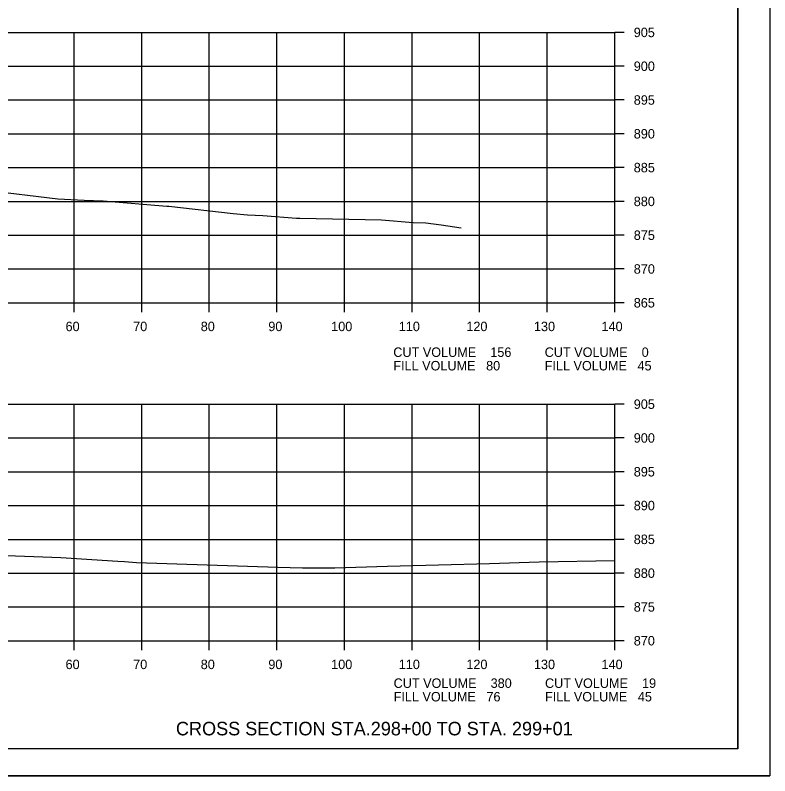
# Model space of a CAD drawing. Extents: x 1486524 to 1499135, y 326561 to 337924.
# Drawn here: x 1489034.2 to 1489145.8, y 333632.7 to 333745.2 of the extents above; entities that cross this region are included whole.
import ezdxf

# ---------------------------------------------------------------- set-up
doc = ezdxf.new("R2010")
doc.units = 0
for name, color, linetype in [('E_Const Align', 7, 'Continuous'), ('E_Const Align Station', 7, 'Continuous'), ('E_Ownership Information', 7, 'Continuous'), ('E_Property Line', 7, 'Continuous'), ('E_Proposed ROW Fig Annot', 7, 'Continuous'), ('E_Quarter Calls', 7, 'Continuous'), ('E_Tract Number', 7, 'Continuous')]:
    doc.layers.add(name, color=color, linetype=linetype)

msp = doc.modelspace()

# ---------------------------------------------------------------- linework, layer by layer
at = {"layer": 'E_Const Align'}
for p, q in [((1489122.89, 333702.64), (1489122.89, 333742.64)), ((1489124.29, 333742.64), (1489122.89, 333742.64)), ((1489124.29, 333737.64), (1489122.89, 333737.64)), ((1489124.29, 333732.64), (1489122.89, 333732.64)), ((1489124.29, 333727.64), (1489122.89, 333727.64)), ((1489124.29, 333722.64), (1489122.89, 333722.64)), ((1489124.29, 333717.64), (1489122.89, 333717.64)), ((1489124.29, 333712.64), (1489122.89, 333712.64)), ((1489124.29, 333707.64), (1489122.89, 333707.64)), ((1488842.89, 333702.64), (1489122.89, 333702.64)), ((1489042.89, 333701.24), (1489042.89, 333702.64)), ((1489052.89, 333701.24), (1489052.89, 333702.64)), ((1489062.89, 333701.24), (1489062.89, 333702.64)), ((1489072.89, 333701.24), (1489072.89, 333702.64)), ((1489082.89, 333701.24), (1489082.89, 333702.64)), ((1489092.89, 333701.24), (1489092.89, 333702.64)), ((1489102.89, 333701.24), (1489102.89, 333702.64)), ((1489112.89, 333701.24), (1489112.89, 333702.64)), ((1489122.89, 333701.24), (1489122.89, 333702.64)), ((1489124.29, 333702.64), (1489122.89, 333702.64)), ((1489122.89, 333652.64), (1489122.89, 333687.64)), ((1489124.29, 333687.64), (1489122.89, 333687.64)), ((1489124.29, 333682.64), (1489122.89, 333682.64)), ((1489124.29, 333677.64), (1489122.89, 333677.64)), ((1489124.29, 333672.64), (1489122.89, 333672.64)), ((1489124.29, 333667.64), (1489122.89, 333667.64)), ((1489124.29, 333662.64), (1489122.89, 333662.64)), ((1489124.29, 333657.64), (1489122.89, 333657.64)), ((1488842.89, 333652.64), (1489122.89, 333652.64)), ((1489042.89, 333651.24), (1489042.89, 333652.64)), ((1489052.89, 333651.24), (1489052.89, 333652.64)), ((1489062.89, 333651.24), (1489062.89, 333652.64)), ((1489072.89, 333651.24), (1489072.89, 333652.64)), ((1489082.89, 333651.24), (1489082.89, 333652.64)), ((1489092.89, 333651.24), (1489092.89, 333652.64)), ((1489102.89, 333651.24), (1489102.89, 333652.64)), ((1489112.89, 333651.24), (1489112.89, 333652.64)), ((1489122.89, 333651.24), (1489122.89, 333652.64)), ((1489124.29, 333652.64), (1489122.89, 333652.64))]:
    msp.add_line(p, q, dxfattribs=at)
at = {"layer": 'E_Ownership Information'}
for p, q in [((1488842.89, 333742.64), (1489122.89, 333742.64)), ((1489042.89, 333702.64), (1489042.89, 333742.64)), ((1489052.89, 333702.64), (1489052.89, 333742.64)), ((1489062.89, 333702.64), (1489062.89, 333742.64)), ((1489072.89, 333702.64), (1489072.89, 333742.64)), ((1489082.89, 333702.64), (1489082.89, 333742.64)), ((1489092.89, 333702.64), (1489092.89, 333742.64)), ((1489102.89, 333702.64), (1489102.89, 333742.64)), ((1489112.89, 333702.64), (1489112.89, 333742.64)), ((1489122.89, 333702.64), (1489122.89, 333742.64)), ((1488842.89, 333737.64), (1489122.89, 333737.64)), ((1488842.89, 333732.64), (1489122.89, 333732.64)), ((1488842.89, 333727.64), (1489122.89, 333727.64)), ((1488842.89, 333722.64), (1489122.89, 333722.64)), ((1488842.89, 333717.64), (1489122.89, 333717.64)), ((1488842.89, 333712.64), (1489122.89, 333712.64)), ((1488842.89, 333707.64), (1489122.89, 333707.64)), ((1488842.89, 333702.64), (1489122.89, 333702.64)), ((1488842.89, 333687.64), (1489122.89, 333687.64)), ((1489042.89, 333652.64), (1489042.89, 333687.64)), ((1489052.89, 333652.64), (1489052.89, 333687.64)), ((1489062.89, 333652.64), (1489062.89, 333687.64)), ((1489072.89, 333652.64), (1489072.89, 333687.64)), ((1489082.89, 333652.64), (1489082.89, 333687.64)), ((1489092.89, 333652.64), (1489092.89, 333687.64)), ((1489102.89, 333652.64), (1489102.89, 333687.64)), ((1489112.89, 333652.64), (1489112.89, 333687.64)), ((1489122.89, 333652.64), (1489122.89, 333687.64)), ((1488842.89, 333682.64), (1489122.89, 333682.64)), ((1488842.89, 333677.64), (1489122.89, 333677.64)), ((1488842.89, 333672.64), (1489122.89, 333672.64)), ((1488842.89, 333667.64), (1489122.89, 333667.64)), ((1488842.89, 333662.64), (1489122.89, 333662.64)), ((1488842.89, 333657.64), (1489122.89, 333657.64)), ((1488842.89, 333652.64), (1489122.89, 333652.64))]:
    msp.add_line(p, q, dxfattribs=at)
at = {"layer": 'E_Property Line'}
for q in [(1489141.07, 333842.1), (1488824.89, 333636.64)]:
    msp.add_line((1489141.07, 333636.64), q, dxfattribs=at)
at = {"layer": 'E_Quarter Calls'}
msp.add_line((1488812.48, 333632.66), (1489145.82, 333632.66), dxfattribs=at)
for points in [[(1488812.48, 333846), (1489145.82, 333846), (1489145.82, 333632.66), (1488812.48, 333632.66)], [(1489058.81, 333842.1), (1489058.81, 333832.22), (1489094.54, 333832.22), (1489094.54, 333829.3), (1489117.74, 333829.3), (1489117.74, 333804.97), (1489141.07, 333804.97), (1489141.07, 333636.64), (1488824.89, 333636.64), (1488824.89, 333842.1)]]:
    msp.add_lwpolyline(points, close=True, dxfattribs=at)
at = {"layer": 'E_Tract Number'}
for points in [[(1489029.84, 333719.32), (1489040.5, 333718.01), (1489044.38, 333717.84), (1489047.19, 333717.71), (1489056.6, 333716.95), (1489056.9, 333716.93), (1489066.42, 333715.84), (1489068.55, 333715.66), (1489070.81, 333715.54), (1489075.78, 333715.15), (1489076.3, 333715.17), (1489088.39, 333714.92), (1489093.04, 333714.54), (1489094.94, 333714.47), (1489097.21, 333714.16), (1489100.14, 333713.72)], [(1489031.49, 333665.3), (1489040.9, 333664.93), (1489049.35, 333664.43), (1489050.36, 333664.36), (1489052.13, 333664.21), (1489073.05, 333663.54), (1489076.67, 333663.42), (1489081.44, 333663.41), (1489089.24, 333663.65), (1489104.35, 333664.08), (1489111.7, 333664.32), (1489122.89, 333664.49)]]:
    msp.add_lwpolyline(points, dxfattribs=at)

# ---------------------------------------------------------------- texts
at = {"layer": 'E_Const Align Station'}
for s, p in [('905', (1489125.69, 333741.94)), ('900', (1489125.69, 333736.94)), ('895', (1489125.69, 333731.94)), ('890', (1489125.69, 333726.94)), ('885', (1489125.69, 333721.94)), ('880', (1489125.69, 333716.94)), ('875', (1489125.69, 333711.94)), ('870', (1489125.69, 333706.94)), ('865', (1489125.69, 333701.94)), ('60', (1489041.62, 333698.44)), ('70', (1489051.62, 333698.44)), ('80', (1489061.62, 333698.44)), ('90', (1489071.62, 333698.44)), ('100', (1489080.92, 333698.44)), ('110', (1489090.92, 333698.44)), ('120', (1489100.92, 333698.44)), ('130', (1489110.92, 333698.44)), ('140', (1489120.92, 333698.44)), ('CUT VOLUME    156', (1489090.11, 333694.63)), ('CUT VOLUME    0', (1489112.51, 333694.63)), ('FILL VOLUME   80', (1489090.11, 333692.63)), ('FILL VOLUME   45', (1489112.51, 333692.63)), ('905', (1489125.69, 333686.94)), ('900', (1489125.69, 333681.94)), ('895', (1489125.69, 333676.94)), ('890', (1489125.69, 333671.94)), ('885', (1489125.69, 333666.94)), ('880', (1489125.69, 333661.94)), ('875', (1489125.69, 333656.94)), ('870', (1489125.69, 333651.94)), ('60', (1489041.62, 333648.44)), ('70', (1489051.62, 333648.44)), ('80', (1489061.62, 333648.44)), ('90', (1489071.62, 333648.44)), ('100', (1489080.92, 333648.44)), ('110', (1489090.92, 333648.44)), ('120', (1489100.92, 333648.44)), ('130', (1489110.92, 333648.44)), ('140', (1489120.92, 333648.44)), ('CUT VOLUME    380', (1489090.16, 333645.66)), ('CUT VOLUME    19', (1489112.56, 333645.66)), ('FILL VOLUME   76', (1489090.16, 333643.66)), ('FILL VOLUME   45', (1489112.56, 333643.66))]:
    msp.add_text(s, height=1.4, dxfattribs=at).set_placement(p)
at = {"layer": 'E_Proposed ROW Fig Annot'}
msp.add_text('CROSS SECTION STA.298+00 TO STA. 299+01', height=2, dxfattribs=at).set_placement((1489057.95, 333638.64))

doc.saveas('drawing.dxf')
